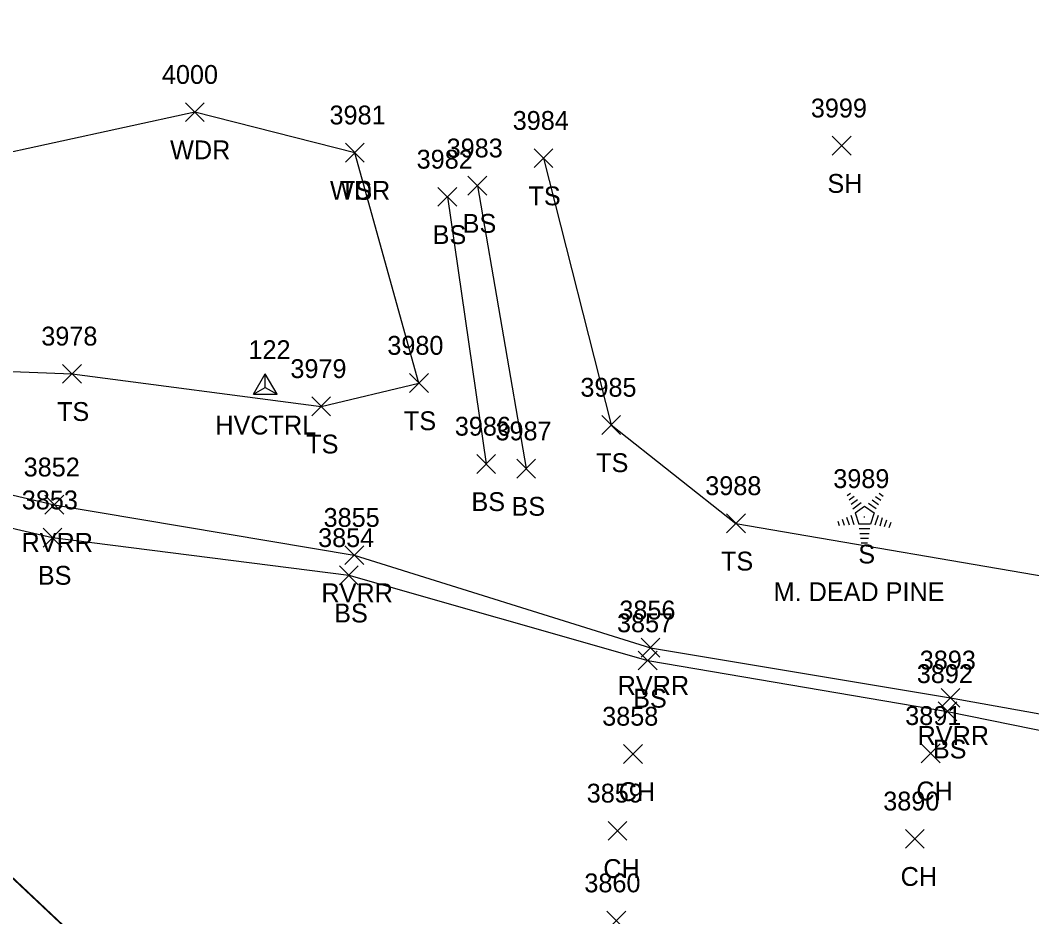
# Model space of a CAD drawing. Extents: x 1647574 to 1652703, y 212895 to 228670.
# Drawn here: x 1649000.9 to 1649108.2, y 227216.4 to 227311.5 of the extents above; entities that cross this region are included whole.
import ezdxf

# ---------------------------------------------------------------- set-up
doc = ezdxf.new("R2010")
doc.units = 0
for name, color, linetype in [('BDC', 7, 'Continuous'), ('C_A', 7, 'Continuous'), ('C_I', 7, 'Continuous'), ('CPSM', 7, 'Continuous'), ('L_A', 7, 'Continuous'), ('L_C', 7, 'Continuous'), ('L_I', 7, 'Continuous'), ('L_TIC', 7, 'Continuous'), ('LAWA', 7, 'Continuous'), ('LAWE', 7, 'Continuous'), ('LELB', 7, 'Continuous'), ('LTC', 7, 'Continuous')]:
    doc.layers.add(name, color=color, linetype=linetype)

msp = doc.modelspace()

# ---------------------------------------------------------------- linework, layer by layer
at = {"layer": 'BDC'}
for points in [[(1649243.4, 226991.01), (1649194.89, 227036.57), (1649144.77, 227083.81), (1649080.19, 227144.73), (1649023.11, 227198.76), (1648965.38, 227253.07), (1648915.01, 227300.54), (1648862.79, 227349.77)], [(1649243.53, 226991.1), (1649195.07, 227036.68), (1649144.94, 227083.85), (1649080.28, 227144.79), (1649023.25, 227198.71), (1648965.39, 227253.22), (1648915.18, 227300.61), (1648862.96, 227349.86)]]:
    msp.add_lwpolyline(points, dxfattribs=at)
at = {"layer": 'CPSM'}
for p, q in [((1649025.64, 227271.83), (1649026.89, 227273.99)), ((1649028.14, 227271.83), (1649026.89, 227273.99)), ((1649026.89, 227272.55), (1649026.89, 227273.99)), ((1649025.64, 227271.83), (1649026.89, 227272.55)), ((1649026.89, 227272.55), (1649026.89, 227272.55)), ((1649026.89, 227272.55), (1649028.14, 227271.83)), ((1649025.64, 227271.83), (1649028.14, 227271.83))]:
    msp.add_line(p, q, dxfattribs=at)
at = {"layer": 'L_TIC'}
for points in [[(1649018.42, 227300.75), (1649020.42, 227302.75)], [(1649020.42, 227300.75), (1649018.42, 227302.75)], [(1649087.02, 227297.19), (1649089.02, 227299.19)], [(1649089.02, 227297.19), (1649087.02, 227299.19)], [(1649035.39, 227296.45), (1649037.39, 227298.45)], [(1649037.39, 227296.45), (1649035.39, 227298.45)], [(1649035.39, 227296.45), (1649037.39, 227298.45)], [(1649037.39, 227296.45), (1649035.39, 227298.45)], [(1649055.39, 227295.87), (1649057.39, 227297.87)], [(1649057.39, 227295.87), (1649055.39, 227297.87)], [(1649048.38, 227292.95), (1649050.38, 227294.95)], [(1649050.38, 227292.95), (1649048.38, 227294.95)], [(1649045.2, 227291.76), (1649047.2, 227293.76)], [(1649047.2, 227291.76), (1649045.2, 227293.76)], [(1649005.39, 227272.99), (1649007.39, 227274.99)], [(1649007.39, 227272.99), (1649005.39, 227274.99)], [(1649042.18, 227272.01), (1649044.18, 227274.01)], [(1649044.18, 227272.01), (1649042.18, 227274.01)], [(1649031.82, 227269.54), (1649033.82, 227271.54)], [(1649033.82, 227269.54), (1649031.82, 227271.54)], [(1649062.57, 227267.56), (1649064.57, 227269.56)], [(1649064.57, 227267.56), (1649062.57, 227269.56)], [(1649049.31, 227263.43), (1649051.31, 227265.43)], [(1649051.31, 227263.43), (1649049.31, 227265.43)], [(1649053.56, 227262.93), (1649055.56, 227264.93)], [(1649055.56, 227262.93), (1649053.56, 227264.93)], [(1649003.52, 227259.1), (1649005.52, 227261.1)], [(1649005.52, 227259.1), (1649003.52, 227261.1)], [(1649075.81, 227257.12), (1649077.81, 227259.12)], [(1649077.81, 227257.12), (1649075.81, 227259.12)], [(1649003.32, 227255.61), (1649005.32, 227257.61)], [(1649005.32, 227255.61), (1649003.32, 227257.61)], [(1649035.33, 227253.75), (1649037.33, 227255.75)], [(1649037.33, 227253.75), (1649035.33, 227255.75)], [(1649034.75, 227251.61), (1649036.75, 227253.61)], [(1649036.75, 227251.61), (1649034.75, 227253.61)], [(1649066.75, 227243.93), (1649068.75, 227245.93)], [(1649068.75, 227243.93), (1649066.75, 227245.93)], [(1649066.45, 227242.57), (1649068.45, 227244.57)], [(1649068.45, 227242.57), (1649066.45, 227244.57)], [(1649098.56, 227238.62), (1649100.56, 227240.62)], [(1649100.56, 227238.62), (1649098.56, 227240.62)], [(1649098.25, 227237.18), (1649100.25, 227239.18)], [(1649100.25, 227237.18), (1649098.25, 227239.18)], [(1649064.88, 227232.66), (1649066.88, 227234.66)], [(1649066.88, 227232.66), (1649064.88, 227234.66)], [(1649096.45, 227232.73), (1649098.45, 227234.73)], [(1649098.45, 227232.73), (1649096.45, 227234.73)], [(1649063.25, 227224.5), (1649065.25, 227226.5)], [(1649065.25, 227224.5), (1649063.25, 227226.5)], [(1649094.78, 227223.66), (1649096.78, 227225.66)], [(1649096.78, 227223.66), (1649094.78, 227225.66)], [(1649063.12, 227214.98), (1649065.12, 227216.98)], [(1649065.12, 227214.98), (1649063.12, 227216.98)]]:
    msp.add_lwpolyline(points, dxfattribs=at)
at = {"layer": 'LAWA'}
msp.add_lwpolyline([(1649036.39, 227297.45), (1649019.42, 227301.75), (1648997.01, 227296.87), (1648972.27, 227315.92), (1648947.52, 227320.89), (1648911.56, 227329), (1648891.16, 227347.34), (1648874.09, 227360.76)], dxfattribs=at)
at = {"layer": 'LAWE'}
msp.add_lwpolyline([(1648523.62, 227464.44), (1648558.32, 227431.33), (1648577.14, 227410.1), (1648589.54, 227390.22), (1648614.46, 227367.16), (1648643.49, 227349.68), (1648671.91, 227332.59), (1648697.56, 227323.9), (1648718.58, 227316.22), (1648748.46, 227309.79), (1648786.4, 227302.27), (1648830.69, 227294.49), (1648864.9, 227288.6), (1648895.3, 227284.45), (1648918.11, 227285.91), (1648972.01, 227267.7), (1649004.52, 227260.1), (1649036.33, 227254.75), (1649067.75, 227244.93), (1649099.56, 227239.62), (1649133.34, 227233.56), (1649168.72, 227227.53), (1649200.78, 227221.11), (1649219.75, 227218.74)], dxfattribs=at)
at = {"layer": 'LELB'}
for points in [[(1648624.78, 227367.39), (1648661.56, 227343.25), (1648687.99, 227330.79), (1648710.88, 227324.59), (1648732.4, 227320.11), (1648758.29, 227314.94), (1648781.98, 227308.53), (1648826.95, 227303.5), (1648863.73, 227300.17), (1648907.54, 227292.02), (1648945.17, 227284.73), (1648987.25, 227274.74), (1649006.39, 227273.99), (1649032.82, 227270.54), (1649043.18, 227273.01), (1649036.39, 227297.45)], [(1648785.47, 227299.55), (1648829.47, 227290.76), (1648865.22, 227283.83), (1648894.89, 227281.32), (1648915.21, 227276.63), (1648970.74, 227264.41), (1649004.32, 227256.61), (1649035.75, 227252.61), (1649067.45, 227243.57), (1649099.25, 227238.18), (1649133.36, 227231.23), (1649168.07, 227224.49), (1649200.36, 227218.77), (1649219.23, 227216.61)], [(1649056.39, 227296.87), (1649063.57, 227268.56), (1649076.81, 227258.12), (1649113.53, 227251.82), (1649150.05, 227243.87), (1649187.05, 227236.48), (1649233.79, 227229.39)], [(1649049.38, 227293.95), (1649054.56, 227263.93)], [(1649046.2, 227292.76), (1649050.31, 227264.43)]]:
    msp.add_lwpolyline(points, dxfattribs=at)
at = {"layer": 'LTC'}
for p, q in [((1649088.59, 227261.08), (1649088.94, 227261.34)), ((1649088.8, 227260.61), (1649089.33, 227261)), ((1649089.01, 227260.15), (1649089.71, 227260.66)), ((1649089.22, 227259.68), (1649090.1, 227260.32)), ((1649090.87, 227260.28), (1649091.68, 227259.69)), ((1649091.24, 227260.62), (1649091.92, 227260.13)), ((1649091.62, 227260.97), (1649092.17, 227260.57)), ((1649091.99, 227261.32), (1649092.41, 227261.02)), ((1649089.44, 227259.23), (1649090.45, 227259.96)), ((1649089.44, 227259.23), (1649089.83, 227258.03)), ((1649090.45, 227259.96), (1649091.45, 227259.24)), ((1649091.45, 227259.24), (1649091.06, 227258.03)), ((1649087.62, 227258.36), (1649087.77, 227257.89)), ((1649088.08, 227258.58), (1649088.29, 227257.92)), ((1649088.53, 227258.79), (1649088.8, 227257.96)), ((1649088.99, 227259.01), (1649089.32, 227257.99)), ((1649091.89, 227258.97), (1649091.55, 227257.93)), ((1649092.33, 227258.72), (1649092.05, 227257.83)), ((1649092.78, 227258.47), (1649092.54, 227257.74)), ((1649093.22, 227258.22), (1649093.03, 227257.64)), ((1649091.06, 227258.03), (1649089.83, 227258.03)), ((1649091.02, 227257.53), (1649089.88, 227257.53)), ((1649090.94, 227257.03), (1649089.95, 227257.03)), ((1649090.85, 227256.53), (1649090.02, 227256.53)), ((1649090.77, 227256.03), (1649090.09, 227256.03))]:
    msp.add_line(p, q, dxfattribs=at)

# ---------------------------------------------------------------- texts
at = {"layer": 'C_A'}
msp.add_text('HVCTRL', height=2, dxfattribs=at).set_placement((1649021.59, 227267.55))
at = {"layer": 'C_I'}
msp.add_text('122', height=2, dxfattribs=at).set_placement((1649025.1, 227275.55))
at = {"layer": 'L_A'}
for s, p in [('WDR', (1649016.79, 227296.75)), ('SH', (1649086.51, 227293.19)), ('WDR', (1649033.75, 227292.45)), ('TS', (1649034.8, 227292.45)), ('TS', (1649054.8, 227291.87)), ('BS', (1649047.82, 227288.95)), ('BS', (1649044.64, 227287.76)), ('TS', (1649004.8, 227268.99)), ('TS', (1649041.59, 227268.01)), ('TS', (1649031.23, 227265.54)), ('TS', (1649061.98, 227263.56)), ('BS', (1649048.75, 227259.43)), ('BS', (1649053, 227258.93)), ('RVRR', (1649001.03, 227255.1)), ('TS', (1649075.22, 227253.12)), ('S', (1649089.78, 227253.87)), ('BS', (1649002.76, 227251.61)), ('RVRR', (1649032.84, 227249.75)), ('BS', (1649034.19, 227247.61)), ('RVRR', (1649064.26, 227239.93)), ('BS', (1649065.9, 227238.57)), ('RVRR', (1649096.07, 227234.62)), ('BS', (1649097.69, 227233.18)), ('CH', (1649064.37, 227228.66)), ('CH', (1649095.94, 227228.73)), ('CH', (1649062.74, 227220.5)), ('CH', (1649094.27, 227219.66))]:
    msp.add_text(s, height=2, dxfattribs=at).set_placement(p)
at = {"layer": 'L_C'}
msp.add_text('M. DEAD PINE', height=2, dxfattribs=at).set_placement((1649080.8, 227249.87))
at = {"layer": 'L_I'}
for s, p in [('4000', (1649015.92, 227304.75)), ('3999', (1649084.75, 227301.19)), ('3981', (1649033.7, 227300.45)), ('3981', (1649033.7, 227300.45)), ('3984', (1649053.13, 227299.87)), ('3983', (1649046.12, 227296.95)), ('3982', (1649042.94, 227295.76)), ('3978', (1649003.13, 227276.99)), ('3980', (1649039.83, 227276.01)), ('3979', (1649029.55, 227273.54)), ('3985', (1649060.31, 227271.56)), ('3986', (1649046.99, 227267.43)), ('3987', (1649051.3, 227266.93)), ('3852', (1649001.26, 227263.1)), ('3989', (1649087.13, 227261.87)), ('3988', (1649073.55, 227261.12)), ('3853', (1649001.06, 227259.61)), ('3855', (1649033.07, 227257.75)), ('3854', (1649032.49, 227255.61)), ('3856', (1649064.44, 227247.93)), ('3857', (1649064.19, 227246.57)), ('3893', (1649096.3, 227242.62)), ('3892', (1649095.99, 227241.18)), ('3858', (1649062.62, 227236.66)), ('3891', (1649094.76, 227236.73)), ('3859', (1649060.98, 227228.5)), ('3890', (1649092.43, 227227.66)), ('3860', (1649060.73, 227218.98))]:
    msp.add_text(s, height=2, dxfattribs=at).set_placement(p)
at = {"layer": 'LTC'}
msp.add_text('.', height=1.04, rotation=270, dxfattribs=at).set_placement((1649090.34, 227258.98))

doc.saveas('drawing.dxf')
